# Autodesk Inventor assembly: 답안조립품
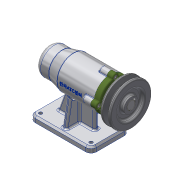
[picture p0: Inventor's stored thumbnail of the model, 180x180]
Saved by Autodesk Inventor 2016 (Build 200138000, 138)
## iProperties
Created: 2019-07
Part Number: 답안조립품
Material: 일반
Document SubType Name: Assembly
Designer: 3sil_cad003
Author: 3sil_cad003
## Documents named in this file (12)
- C:\Users\3sil_cad003\Desktop\490704V1003\답안조립품.iam
- C:\Users\3sil_cad003\Desktop\490704V1003\본체.ipt
- C:\Users\3sil_cad003\Desktop\490704V1003\축.ipt
- C:\Users\3sil_cad003\Desktop\490704V1003\키 5 x 5 x 16.ipt
- C:\Users\3sil_cad003\Desktop\490704V1003\베어링 51202.ipt
- C:\Users\3sil_cad003\Desktop\490704V1003\어댑터슬리브.ipt
- C:\Users\3sil_cad003\Desktop\490704V1003\베어링 6004.ipt
- C:\Users\3sil_cad003\Desktop\490704V1003\볼트 M4.ipt
- C:\Users\3sil_cad003\Desktop\490704V1003\커버.ipt
- C:\Users\3sil_cad003\Desktop\490704V1003\오일 실.ipt
- C:\Users\3sil_cad003\Desktop\490704V1003\멈춤나사 M3.ipt
- C:\Users\3sil_cad003\Desktop\490704V1003\V벨트풀리.ipt
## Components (1 placed, 1 different names)
1. V벨트풀리:1
